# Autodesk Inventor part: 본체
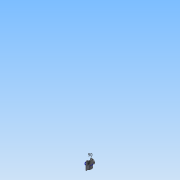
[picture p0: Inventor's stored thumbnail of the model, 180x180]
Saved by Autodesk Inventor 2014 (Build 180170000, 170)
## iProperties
Created: 2015-01
Part Number: 본체
Material: 일반
Document SubType Name: Modeling
Designer: net
Density: 1 g/cm^3
Appearance: 기본값
Author: net
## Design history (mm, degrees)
sketch "스케치1"
  geometry: C1 r 50 at (0, 0); 1 further point
  constraints: 1 centre point, 1 coincident
  dimensions: "d0" = 100 diameter of C1
extrude "돌출1" new body sketch "스케치1" distance "d1" = 112; taper "d2" = 0 deg
sketch "스케치2"
  geometry: C1 r 50 at (0, 0) reference; C2 r 38 at (0, 0)
  constraints: 1 centre point, 1 coincident
  dimensions: "d3" = 76 diameter of C2
extrude "돌출2" join sketch "스케치2" distance "d4" = 5; taper "d5" = 0 deg
node "작업 평면1"
sketch "스케치3"
  geometry: L1 (-50, 0)-(50, 0) reference; L2 (50, 0)-(50, 112) reference; C1 r 38 at (0, 56); 2 further points
  constraints: 1 centre point, 1 horizontal alignment, 1 midpoint, 1 vertical alignment
  dimensions: "d7" = 76 diameter of C1
extrude "돌출3" join sketch "스케치3" stored distance "d9" = 5; taper "d10" = 0 deg
sketch "스케치4"
  geometry: C1 r 50 at (0, 0) reference; C2 r 38 at (0, 0)
  constraints: 1 centre point, 1 coincident
  dimensions: "d11" = 76 diameter of C2
extrude "돌출4" join sketch "스케치4" distance "d12" = 5; taper "d13" = 0 deg
hole "구멍1" diameter "d16" = 54; stored, may be unused: countersink angle "d20" = 90 deg, drill point angle "d22" = 0 deg; dims "d14" = 10, "d15" = 10, "d17" = 6, "d18" = 4, "d19" = 2, "d21" = 12
node "작업 평면2"
sketch "스케치5"
  geometry: C1 r 45 at (0, 0); 1 further point
  constraints: 1 centre point, 1 coincident
  dimensions: "d23" = 90 diameter of C1
hole "구멍2" diameter "d28" = 54; stored, may be unused: countersink angle "d32" = 90 deg, drill point angle "d34" = 0 deg; dims "d26" = 10, "d27" = 10, "d29" = 6, "d30" = 4, "d31" = 2, "d33" = 13
sketch "스케치6" dims "d38" = 64
  geometry: C1 r 27 at (0, 0) reference; C2 r 38 at (0, 0) reference; 2 further points
  constraints: 2 vertical alignment, 1 coincident, 2 other
hole "구멍3" sketch "스케치6" at (0, 32) diameter "d39" = 3.459; stored, may be unused: countersink angle "d43" = 90 deg, drill point angle "d45" = 118 deg; dims "d40" = 8, "d41" = 4, "d42" = 2, "d44" = 10
sketch "스케치7" dims "d49" = 64
  geometry: C1 r 27 at (0, 0) reference; C2 r 38 at (0, 0) reference; 2 further points
  constraints: 2 vertical alignment, 1 coincident, 2 other
hole "구멍4" sketch "스케치7" at (0, 32) diameter "d50" = 3.459; stored, may be unused: countersink angle "d54" = 90 deg, drill point angle "d56" = 118 deg; dims "d51" = 8, "d52" = 4, "d53" = 2, "d55" = 10
sketch "스케치8" dims "d60" = 64
  geometry: C1 r 38 at (0, 0) reference; 3 further points
  constraints: 2 vertical alignment, 1 coincident, 2 other
hole "구멍5" sketch "스케치8" at (0, 32) diameter "d61" = 3.459; stored, may be unused: countersink angle "d65" = 90 deg, drill point angle "d67" = 118 deg; dims "d62" = 8, "d63" = 4, "d64" = 2, "d66" = 10
fillet "모깎기3" dims "d82" = 3
chamfer "모따기1" distance "d83" = 1; stored, may be unused: second distance "d84" = 2, angle "d85" = 45 deg
fillet "모깎기4" dims "d86" = 3
fillet "모깎기5" dims "d87" = 3
fillet "모깎기6" dims "d88" = 3
node "작업 평면5"
sketch "스케치10"
  geometry: L1 (-39.336, -30.865)-(-48, -80); L2 (-27.088, -42.026)-(-33.784, -80); L3 (-48, -80)-(-33.784, -80); C1 r 45 at (0, 0) reference; A1 r 50 centre (0, 0) between (-39.336, -30.865) and (-27.088, -42.026) reference; 1 further point
  constraints: 6 end point, 2 point on circle, 1 horizontal
  dimensions: "d92" = 14 distance between parallel lines of L2 L1; "d93" = 80 distance from line of point (0, 0) L3; "d94" = 100 deg angle of L3 L1; "d95" = 48 horizontal distance of point (0, 0) L1.end
extrude "돌출6" join sketch "스케치10" stored distance "d96" = 80; taper "d97" = 0 deg
fillet "모깎기7" dims "d98" = 3
fillet "모깎기8" dims "d99" = 3
node "작업 평면6"
node "작업 평면7"
sketch "스케치11"
  geometry: L1 (-6, 30)-(6, 30); L2 (6, 30)-(6, 84); L3 (6, 84)-(-6, 84); L4 (-6, 84)-(-6, 30); L5 (80, 19)-(80, 93) reference; L6 (50, 3)-(50, 109) reference; L7 (-6, 57)-(6, 57); L8 (-38, -5)-(38, -5) reference; 4 further points
  constraints: 10 end point, 5 midpoint, 3 horizontal, 2 vertical alignment, 1 coincident
  dimensions: "d101" = 54 distance of L3.end L1.start; "d102" = 12 distance between parallel lines of L2 L4; "d103" = 62 distance between parallel lines of L8 L7
extrude "돌출7" join sketch "스케치11" stored distance "d104" = 80; taper "d105" = 0 deg
sketch "스케치12"
  geometry: L1 (30, 6)-(30, -6) reference; L2 (-5, 38)-(-5, -38) reference; 3 further points
  constraints: 1 horizontal alignment, 1 midpoint, 1 other
  dimensions: "d106" = 62 distance from line of L2 point (57, 0)
feature "엠보싱1" sketch "스케치12" dims "d107" = 0.5, "d108" = 0
node "작업 평면9"
sketch "스케치14"
  geometry: C1 r 45 at (0, 0); 1 further point
  constraints: 1 centre point, 1 coincident
  dimensions: "d114" = 90 diameter of C1
extrude "돌출9" cut sketch "스케치14" distance "d115" = 97; taper "d116" = 0 deg
fillet "모깎기9" dims "d120" = 3
sketch "스케치17"
  geometry: C1 r 38 at (0, 0) reference; C2 r 27 at (0, 0); 1 further point
  constraints: 1 centre point, 1 coincident
  dimensions: "d121" = 54 diameter of C2
extrude "돌출11" cut sketch "스케치17" stored distance "d122" = 97; taper "d123" = 0 deg
fillet "모깎기10" dims "d124" = 3
chamfer "모따기2" distance "d125" = 1; stored, may be unused: second distance "d126" = 2, angle "d127" = 45 deg
sketch "스케치16"
  geometry: C1 r 45 at (0, 0); 1 further point
  constraints: 1 centre point, 1 coincident
  dimensions: "d117" = 90 diameter of C1
extrude "돌출10" join sketch "스케치16" distance "d118" = 97; taper "d119" = 0 deg
node "작업 평면8"
sketch "스케치13"
  geometry: C1 r 45 at (0, 0); 1 further point
  constraints: 1 centre point, 1 coincident
  dimensions: "d110" = 90 diameter of C1
extrude "돌출8" cut sketch "스케치13" distance "d111" = 97; taper "d112" = 0 deg
sketch "스케치9"
  geometry: L1 (32, 50.961)-(33.73, 52) reference; L2 (33.73, 52)-(33.73, 62) reference; L3 (33.73, 62)-(38, 62) reference; L4 (38, 62)-(38, 33.586) reference; L5 (-38, 33.586)-(-38, 62) reference; L6 (-38, 62)-(-33.73, 62) reference; L7 (-33.73, 62)-(-33.73, 52) reference; L8 (-33.73, 52)-(-32, 50.961) reference; L9 (-32, 50.961)-(-30.27, 52) reference; L10 (-30.27, 52)-(-30.27, 62) reference; L11 (-30.27, 62)-(-27, 62) reference; L12 (-27, 62)-(-27, 37.47) reference; L13 (27, 37.47)-(27, 62) reference; L14 (27, 62)-(30.27, 62) reference; L15 (30.27, 62)-(30.27, 52) reference; L16 (30.27, 52)-(32, 50.961) reference; L17 (-34.835, -28.487)-(-43.918, -80); L18 (-43.918, -80)-(-31.366, -80); L19 (-31.366, -80)-(-23.975, -38.082); A1 r 50 centre (0, 0) between (-38.679, 31.685) and (38.679, 31.685) reference; A2 r 45 centre (0, 0) between (-28.125, 35.128) and (28.125, 35.128) reference; 1 further point
  constraints: 6 end point, 2 point on circle, 1 horizontal, 4 other
  dimensions: "d89" = 100 deg angle of L18 L17; "d90" = 80 distance from line of point (0, 0) L18; "d91" = 80 deg angle of L19 L18
  node "절단 모서리 투영1"
node "작업 평면4"
  node "작업 평면3"
node "솔리드1"
pattern_circular "원형 패턴1" dims angle "d47" = 360 deg
pattern_circular "원형 패턴2" dims angle "d58" = 360 deg
pattern_circular "원형 패턴3" dims angle "d69" = 360 deg
mirror "대칭1"
other parameters: "d6" = 62, "d35" = 12, "d100" = 2, "d109" = -13, "d113" = -12
